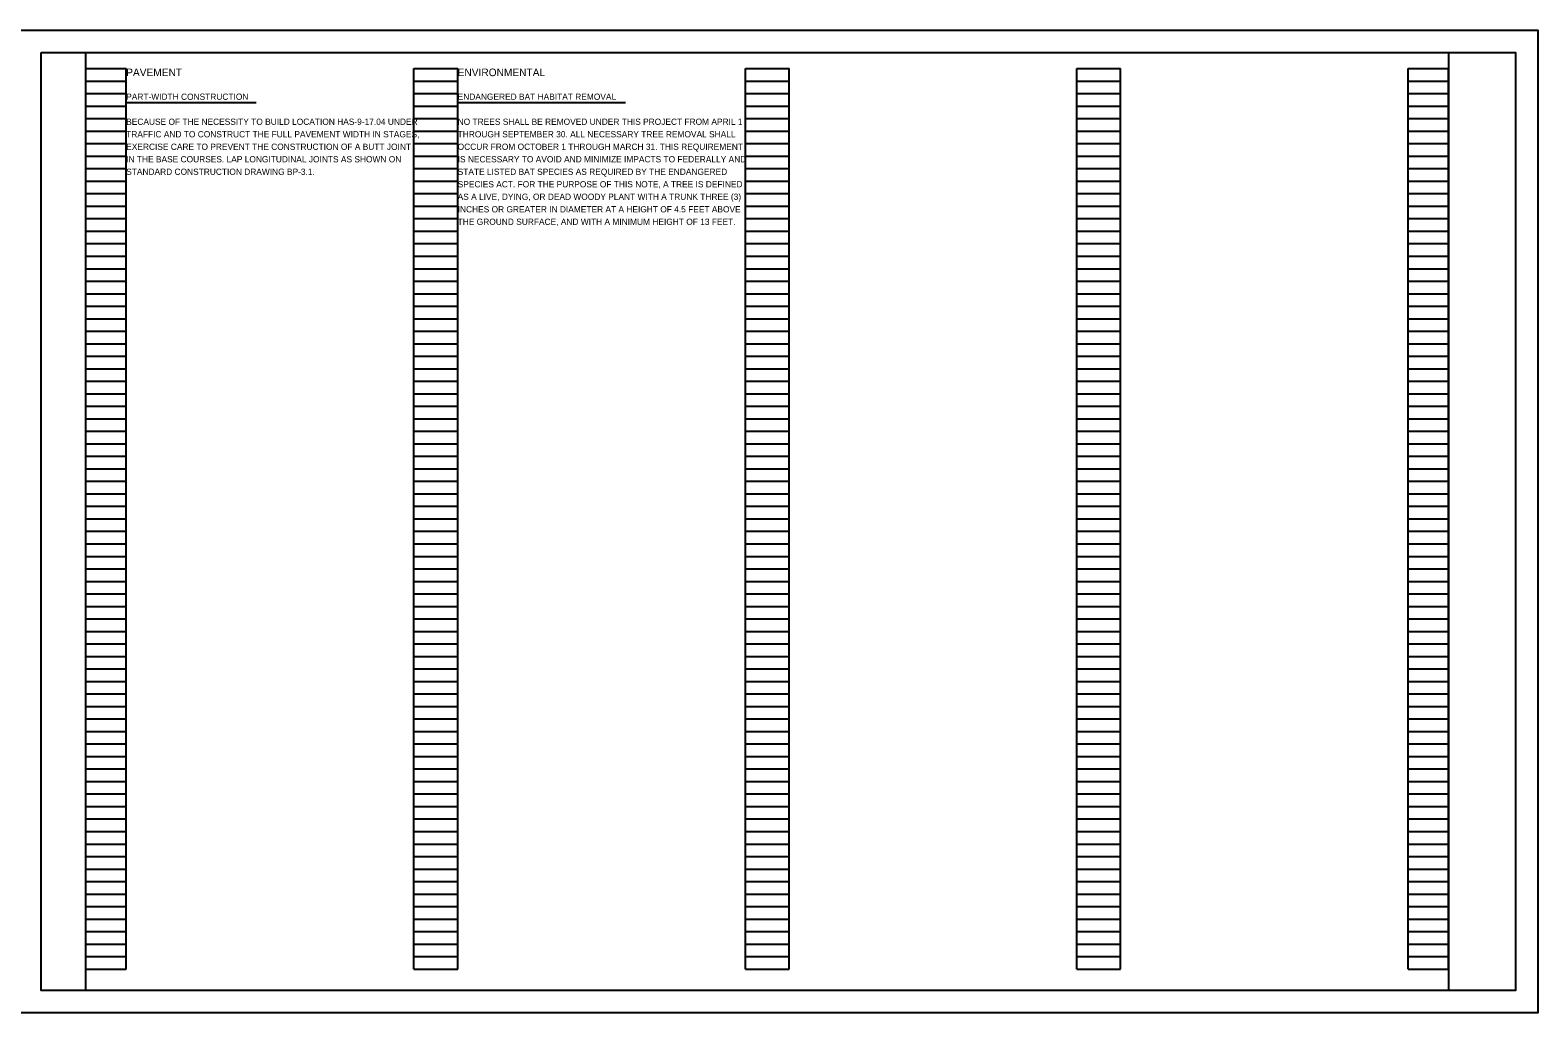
# Model space of a CAD drawing. Extents: x 0 to 102, y 0 to 22.
# Drawn here: x 68.25 to 102, y 0 to 22 of the extents above; entities that cross this region are included whole.
import ezdxf

# ---------------------------------------------------------------- set-up
doc = ezdxf.new("R2010")
doc.units = 0
doc.layers.add('SC_Scratch1', color=7, linetype='Continuous')
doc.layers.add('SH_Text', color=7, linetype='Continuous')

msp = doc.modelspace()

# ---------------------------------------------------------------- linework, layer by layer
at = {"layer": 'SC_Scratch1'}
for p, q in [((69.5, 0.98), (69.5, 21.14)), ((69.5, 21.14), (70.4, 21.14)), ((70.4, 0.98), (70.4, 21.14)), ((76.84, 0.98), (76.84, 21.14)), ((76.84, 21.14), (77.82, 21.14)), ((77.82, 0.98), (77.82, 21.14)), ((84.26, 0.98), (84.26, 21.14)), ((84.26, 21.14), (85.24, 21.14)), ((85.24, 0.98), (85.24, 21.14)), ((91.68, 0.98), (91.68, 21.14)), ((91.68, 21.14), (92.66, 21.14)), ((92.66, 0.98), (92.66, 21.14)), ((99.1, 0.98), (99.1, 21.14)), ((99.1, 21.14), (100, 21.14)), ((100, 0.98), (100, 21.14)), ((69.5, 20.86), (70.4, 20.86)), ((76.84, 20.86), (77.82, 20.86)), ((84.26, 20.86), (85.24, 20.86)), ((91.68, 20.86), (92.66, 20.86)), ((99.1, 20.86), (100, 20.86)), ((69.5, 20.58), (70.4, 20.58)), ((69.5, 20.3), (70.4, 20.3)), ((76.84, 20.58), (77.82, 20.58)), ((76.84, 20.3), (77.82, 20.3)), ((84.26, 20.58), (85.24, 20.58)), ((84.26, 20.3), (85.24, 20.3)), ((91.68, 20.58), (92.66, 20.58)), ((91.68, 20.3), (92.66, 20.3)), ((99.1, 20.58), (100, 20.58)), ((99.1, 20.3), (100, 20.3)), ((69.5, 20.02), (70.4, 20.02)), ((76.84, 20.02), (77.82, 20.02)), ((84.26, 20.02), (85.24, 20.02)), ((91.68, 20.02), (92.66, 20.02)), ((99.1, 20.02), (100, 20.02)), ((69.5, 19.74), (70.4, 19.74)), ((76.84, 19.74), (77.82, 19.74)), ((84.26, 19.74), (85.24, 19.74)), ((91.68, 19.74), (92.66, 19.74)), ((99.1, 19.74), (100, 19.74)), ((69.5, 19.46), (70.4, 19.46)), ((76.84, 19.46), (77.82, 19.46)), ((84.26, 19.46), (85.24, 19.46)), ((91.68, 19.46), (92.66, 19.46)), ((99.1, 19.46), (100, 19.46)), ((69.5, 19.18), (70.4, 19.18)), ((76.84, 19.18), (77.82, 19.18)), ((84.26, 19.18), (85.24, 19.18)), ((91.68, 19.18), (92.66, 19.18)), ((99.1, 19.18), (100, 19.18)), ((69.5, 18.9), (70.4, 18.9)), ((69.5, 18.62), (70.4, 18.62)), ((76.84, 18.9), (77.82, 18.9)), ((76.84, 18.62), (77.82, 18.62)), ((84.26, 18.9), (85.24, 18.9)), ((84.26, 18.62), (85.24, 18.62)), ((91.68, 18.9), (92.66, 18.9)), ((91.68, 18.62), (92.66, 18.62)), ((99.1, 18.9), (100, 18.9)), ((99.1, 18.62), (100, 18.62)), ((69.5, 18.34), (70.4, 18.34)), ((76.84, 18.34), (77.82, 18.34)), ((84.26, 18.34), (85.24, 18.34)), ((91.68, 18.34), (92.66, 18.34)), ((99.1, 18.34), (100, 18.34)), ((69.5, 18.06), (70.4, 18.06)), ((76.84, 18.06), (77.82, 18.06)), ((84.26, 18.06), (85.24, 18.06)), ((91.68, 18.06), (92.66, 18.06)), ((99.1, 18.06), (100, 18.06)), ((69.5, 17.78), (70.4, 17.78)), ((76.84, 17.78), (77.82, 17.78)), ((84.26, 17.78), (85.24, 17.78)), ((91.68, 17.78), (92.66, 17.78)), ((99.1, 17.78), (100, 17.78)), ((69.5, 17.5), (70.4, 17.5)), ((69.5, 17.22), (70.4, 17.22)), ((76.84, 17.5), (77.82, 17.5)), ((76.84, 17.22), (77.82, 17.22)), ((84.26, 17.5), (85.24, 17.5)), ((84.26, 17.22), (85.24, 17.22)), ((91.68, 17.5), (92.66, 17.5)), ((91.68, 17.22), (92.66, 17.22)), ((99.1, 17.5), (100, 17.5)), ((99.1, 17.22), (100, 17.22)), ((69.5, 16.94), (70.4, 16.94)), ((76.84, 16.94), (77.82, 16.94)), ((84.26, 16.94), (85.24, 16.94)), ((91.68, 16.94), (92.66, 16.94)), ((99.1, 16.94), (100, 16.94)), ((69.5, 16.66), (70.4, 16.66)), ((76.84, 16.66), (77.82, 16.66)), ((84.26, 16.66), (85.24, 16.66)), ((91.68, 16.66), (92.66, 16.66)), ((99.1, 16.66), (100, 16.66)), ((69.5, 16.38), (70.4, 16.38)), ((76.84, 16.38), (77.82, 16.38)), ((84.26, 16.38), (85.24, 16.38)), ((91.68, 16.38), (92.66, 16.38)), ((99.1, 16.38), (100, 16.38)), ((69.5, 16.1), (70.4, 16.1)), ((76.84, 16.1), (77.82, 16.1)), ((84.26, 16.1), (85.24, 16.1)), ((91.68, 16.1), (92.66, 16.1)), ((99.1, 16.1), (100, 16.1)), ((69.5, 15.82), (70.4, 15.82)), ((69.5, 15.54), (70.4, 15.54)), ((76.84, 15.82), (77.82, 15.82)), ((76.84, 15.54), (77.82, 15.54)), ((84.26, 15.82), (85.24, 15.82)), ((84.26, 15.54), (85.24, 15.54)), ((91.68, 15.82), (92.66, 15.82)), ((91.68, 15.54), (92.66, 15.54)), ((99.1, 15.82), (100, 15.82)), ((99.1, 15.54), (100, 15.54)), ((69.5, 15.26), (70.4, 15.26)), ((76.84, 15.26), (77.82, 15.26)), ((84.26, 15.26), (85.24, 15.26)), ((91.68, 15.26), (92.66, 15.26)), ((99.1, 15.26), (100, 15.26)), ((69.5, 14.98), (70.4, 14.98)), ((76.84, 14.98), (77.82, 14.98)), ((84.26, 14.98), (85.24, 14.98)), ((91.68, 14.98), (92.66, 14.98)), ((99.1, 14.98), (100, 14.98)), ((69.5, 14.7), (70.4, 14.7)), ((76.84, 14.7), (77.82, 14.7)), ((84.26, 14.7), (85.24, 14.7)), ((91.68, 14.7), (92.66, 14.7)), ((99.1, 14.7), (100, 14.7)), ((69.5, 14.42), (70.4, 14.42)), ((76.84, 14.42), (77.82, 14.42)), ((84.26, 14.42), (85.24, 14.42)), ((91.68, 14.42), (92.66, 14.42)), ((99.1, 14.42), (100, 14.42)), ((69.5, 14.14), (70.4, 14.14)), ((69.5, 13.86), (70.4, 13.86)), ((76.84, 14.14), (77.82, 14.14)), ((76.84, 13.86), (77.82, 13.86)), ((84.26, 14.14), (85.24, 14.14)), ((84.26, 13.86), (85.24, 13.86)), ((91.68, 14.14), (92.66, 14.14)), ((91.68, 13.86), (92.66, 13.86)), ((99.1, 14.14), (100, 14.14)), ((99.1, 13.86), (100, 13.86)), ((69.5, 13.58), (70.4, 13.58)), ((76.84, 13.58), (77.82, 13.58)), ((84.26, 13.58), (85.24, 13.58)), ((91.68, 13.58), (92.66, 13.58)), ((99.1, 13.58), (100, 13.58)), ((69.5, 13.3), (70.4, 13.3)), ((76.84, 13.3), (77.82, 13.3)), ((84.26, 13.3), (85.24, 13.3)), ((91.68, 13.3), (92.66, 13.3)), ((99.1, 13.3), (100, 13.3)), ((69.5, 13.02), (70.4, 13.02)), ((76.84, 13.02), (77.82, 13.02)), ((84.26, 13.02), (85.24, 13.02)), ((91.68, 13.02), (92.66, 13.02)), ((99.1, 13.02), (100, 13.02)), ((69.5, 12.74), (70.4, 12.74)), ((76.84, 12.74), (77.82, 12.74)), ((84.26, 12.74), (85.24, 12.74)), ((91.68, 12.74), (92.66, 12.74)), ((99.1, 12.74), (100, 12.74)), ((69.5, 12.46), (70.4, 12.46)), ((69.5, 12.18), (70.4, 12.18)), ((76.84, 12.46), (77.82, 12.46)), ((76.84, 12.18), (77.82, 12.18)), ((84.26, 12.46), (85.24, 12.46)), ((84.26, 12.18), (85.24, 12.18)), ((91.68, 12.46), (92.66, 12.46)), ((91.68, 12.18), (92.66, 12.18)), ((99.1, 12.46), (100, 12.46)), ((99.1, 12.18), (100, 12.18)), ((69.5, 11.9), (70.4, 11.9)), ((76.84, 11.9), (77.82, 11.9)), ((84.26, 11.9), (85.24, 11.9)), ((91.68, 11.9), (92.66, 11.9)), ((99.1, 11.9), (100, 11.9)), ((69.5, 11.62), (70.4, 11.62)), ((76.84, 11.62), (77.82, 11.62)), ((84.26, 11.62), (85.24, 11.62)), ((91.68, 11.62), (92.66, 11.62)), ((99.1, 11.62), (100, 11.62)), ((69.5, 11.34), (70.4, 11.34)), ((76.84, 11.34), (77.82, 11.34)), ((84.26, 11.34), (85.24, 11.34)), ((91.68, 11.34), (92.66, 11.34)), ((99.1, 11.34), (100, 11.34)), ((69.5, 11.06), (70.4, 11.06)), ((76.84, 11.06), (77.82, 11.06)), ((84.26, 11.06), (85.24, 11.06)), ((91.68, 11.06), (92.66, 11.06)), ((99.1, 11.06), (100, 11.06)), ((69.5, 10.78), (70.4, 10.78)), ((69.5, 10.5), (70.4, 10.5)), ((76.84, 10.78), (77.82, 10.78)), ((76.84, 10.5), (77.82, 10.5)), ((84.26, 10.78), (85.24, 10.78)), ((84.26, 10.5), (85.24, 10.5)), ((91.68, 10.78), (92.66, 10.78)), ((91.68, 10.5), (92.66, 10.5)), ((99.1, 10.78), (100, 10.78)), ((99.1, 10.5), (100, 10.5)), ((69.5, 10.22), (70.4, 10.22)), ((76.84, 10.22), (77.82, 10.22)), ((84.26, 10.22), (85.24, 10.22)), ((91.68, 10.22), (92.66, 10.22)), ((99.1, 10.22), (100, 10.22)), ((69.5, 9.94), (70.4, 9.94)), ((76.84, 9.94), (77.82, 9.94)), ((84.26, 9.94), (85.24, 9.94)), ((91.68, 9.94), (92.66, 9.94)), ((99.1, 9.94), (100, 9.94)), ((69.5, 9.66), (70.4, 9.66)), ((76.84, 9.66), (77.82, 9.66)), ((84.26, 9.66), (85.24, 9.66)), ((91.68, 9.66), (92.66, 9.66)), ((99.1, 9.66), (100, 9.66)), ((69.5, 9.38), (70.4, 9.38)), ((76.84, 9.38), (77.82, 9.38)), ((84.26, 9.38), (85.24, 9.38)), ((91.68, 9.38), (92.66, 9.38)), ((99.1, 9.38), (100, 9.38)), ((69.5, 9.1), (70.4, 9.1)), ((69.5, 8.82), (70.4, 8.82)), ((76.84, 9.1), (77.82, 9.1)), ((76.84, 8.82), (77.82, 8.82)), ((84.26, 9.1), (85.24, 9.1)), ((84.26, 8.82), (85.24, 8.82)), ((91.68, 9.1), (92.66, 9.1)), ((91.68, 8.82), (92.66, 8.82)), ((99.1, 9.1), (100, 9.1)), ((99.1, 8.82), (100, 8.82)), ((69.5, 8.54), (70.4, 8.54)), ((76.84, 8.54), (77.82, 8.54)), ((84.26, 8.54), (85.24, 8.54)), ((91.68, 8.54), (92.66, 8.54)), ((99.1, 8.54), (100, 8.54)), ((69.5, 8.26), (70.4, 8.26)), ((76.84, 8.26), (77.82, 8.26)), ((84.26, 8.26), (85.24, 8.26)), ((91.68, 8.26), (92.66, 8.26)), ((99.1, 8.26), (100, 8.26)), ((69.5, 7.98), (70.4, 7.98)), ((76.84, 7.98), (77.82, 7.98)), ((84.26, 7.98), (85.24, 7.98)), ((91.68, 7.98), (92.66, 7.98)), ((99.1, 7.98), (100, 7.98)), ((69.5, 7.7), (70.4, 7.7)), ((76.84, 7.7), (77.82, 7.7)), ((84.26, 7.7), (85.24, 7.7)), ((91.68, 7.7), (92.66, 7.7)), ((99.1, 7.7), (100, 7.7)), ((69.5, 7.42), (70.4, 7.42)), ((69.5, 7.14), (70.4, 7.14)), ((76.84, 7.42), (77.82, 7.42)), ((76.84, 7.14), (77.82, 7.14)), ((84.26, 7.42), (85.24, 7.42)), ((84.26, 7.14), (85.24, 7.14)), ((91.68, 7.42), (92.66, 7.42)), ((91.68, 7.14), (92.66, 7.14)), ((99.1, 7.42), (100, 7.42)), ((99.1, 7.14), (100, 7.14)), ((69.5, 6.86), (70.4, 6.86)), ((76.84, 6.86), (77.82, 6.86)), ((84.26, 6.86), (85.24, 6.86)), ((91.68, 6.86), (92.66, 6.86)), ((99.1, 6.86), (100, 6.86)), ((69.5, 6.58), (70.4, 6.58)), ((76.84, 6.58), (77.82, 6.58)), ((84.26, 6.58), (85.24, 6.58)), ((91.68, 6.58), (92.66, 6.58)), ((99.1, 6.58), (100, 6.58)), ((69.5, 6.3), (70.4, 6.3)), ((76.84, 6.3), (77.82, 6.3)), ((84.26, 6.3), (85.24, 6.3)), ((91.68, 6.3), (92.66, 6.3)), ((99.1, 6.3), (100, 6.3)), ((69.5, 6.02), (70.4, 6.02)), ((69.5, 5.74), (70.4, 5.74)), ((76.84, 6.02), (77.82, 6.02)), ((76.84, 5.74), (77.82, 5.74)), ((84.26, 6.02), (85.24, 6.02)), ((84.26, 5.74), (85.24, 5.74)), ((91.68, 6.02), (92.66, 6.02)), ((91.68, 5.74), (92.66, 5.74)), ((99.1, 6.02), (100, 6.02)), ((99.1, 5.74), (100, 5.74)), ((69.5, 5.46), (70.4, 5.46)), ((76.84, 5.46), (77.82, 5.46)), ((84.26, 5.46), (85.24, 5.46)), ((91.68, 5.46), (92.66, 5.46)), ((99.1, 5.46), (100, 5.46)), ((69.5, 5.18), (70.4, 5.18)), ((76.84, 5.18), (77.82, 5.18)), ((84.26, 5.18), (85.24, 5.18)), ((91.68, 5.18), (92.66, 5.18)), ((99.1, 5.18), (100, 5.18)), ((69.5, 4.9), (70.4, 4.9)), ((76.84, 4.9), (77.82, 4.9)), ((84.26, 4.9), (85.24, 4.9)), ((91.68, 4.9), (92.66, 4.9)), ((99.1, 4.9), (100, 4.9)), ((69.5, 4.62), (70.4, 4.62)), ((76.84, 4.62), (77.82, 4.62)), ((84.26, 4.62), (85.24, 4.62)), ((91.68, 4.62), (92.66, 4.62)), ((99.1, 4.62), (100, 4.62)), ((69.5, 4.34), (70.4, 4.34)), ((69.5, 4.06), (70.4, 4.06)), ((76.84, 4.34), (77.82, 4.34)), ((76.84, 4.06), (77.82, 4.06)), ((84.26, 4.34), (85.24, 4.34)), ((84.26, 4.06), (85.24, 4.06)), ((91.68, 4.34), (92.66, 4.34)), ((91.68, 4.06), (92.66, 4.06)), ((99.1, 4.34), (100, 4.34)), ((99.1, 4.06), (100, 4.06)), ((69.5, 3.78), (70.4, 3.78)), ((76.84, 3.78), (77.82, 3.78)), ((84.26, 3.78), (85.24, 3.78)), ((91.68, 3.78), (92.66, 3.78)), ((99.1, 3.78), (100, 3.78)), ((69.5, 3.5), (70.4, 3.5)), ((76.84, 3.5), (77.82, 3.5)), ((84.26, 3.5), (85.24, 3.5)), ((91.68, 3.5), (92.66, 3.5)), ((99.1, 3.5), (100, 3.5)), ((69.5, 3.22), (70.4, 3.22)), ((76.84, 3.22), (77.82, 3.22)), ((84.26, 3.22), (85.24, 3.22)), ((91.68, 3.22), (92.66, 3.22)), ((99.1, 3.22), (100, 3.22)), ((69.5, 2.94), (70.4, 2.94)), ((76.84, 2.94), (77.82, 2.94)), ((84.26, 2.94), (85.24, 2.94)), ((91.68, 2.94), (92.66, 2.94)), ((99.1, 2.94), (100, 2.94)), ((69.5, 2.66), (70.4, 2.66)), ((69.5, 2.38), (70.4, 2.38)), ((76.84, 2.66), (77.82, 2.66)), ((76.84, 2.38), (77.82, 2.38)), ((84.26, 2.66), (85.24, 2.66)), ((84.26, 2.38), (85.24, 2.38)), ((91.68, 2.66), (92.66, 2.66)), ((91.68, 2.38), (92.66, 2.38)), ((99.1, 2.66), (100, 2.66)), ((99.1, 2.38), (100, 2.38)), ((69.5, 2.1), (70.4, 2.1)), ((76.84, 2.1), (77.82, 2.1)), ((84.26, 2.1), (85.24, 2.1)), ((91.68, 2.1), (92.66, 2.1)), ((99.1, 2.1), (100, 2.1)), ((69.5, 1.82), (70.4, 1.82)), ((76.84, 1.82), (77.82, 1.82)), ((84.26, 1.82), (85.24, 1.82)), ((91.68, 1.82), (92.66, 1.82)), ((99.1, 1.82), (100, 1.82)), ((69.5, 1.54), (70.4, 1.54)), ((76.84, 1.54), (77.82, 1.54)), ((84.26, 1.54), (85.24, 1.54)), ((91.68, 1.54), (92.66, 1.54)), ((99.1, 1.54), (100, 1.54)), ((69.5, 1.26), (70.4, 1.26)), ((76.84, 1.26), (77.82, 1.26)), ((84.26, 1.26), (85.24, 1.26)), ((91.68, 1.26), (92.66, 1.26)), ((99.1, 1.26), (100, 1.26)), ((69.5, 0.98), (70.4, 0.98)), ((76.84, 0.98), (77.82, 0.98)), ((84.26, 0.98), (85.24, 0.98)), ((91.68, 0.98), (92.66, 0.98)), ((99.1, 0.98), (100, 0.98))]:
    msp.add_line(p, q, dxfattribs=at)
for points in [[(68, 22), (102, 22), (102, 0), (68, 0)], [(68.5, 21.5), (101.5, 21.5), (101.5, 0.5), (68.5, 0.5)], [(69.5, 21.5), (100, 21.5), (100, 0.5), (69.5, 0.5)]]:
    msp.add_lwpolyline(points, close=True, dxfattribs=at)
at = {"layer": 'SH_Text'}
for p, q in [((70.4, 20.379), (73.31, 20.379)), ((77.82, 20.379), (81.575, 20.379))]:
    msp.add_line(p, q, dxfattribs=at)

# ---------------------------------------------------------------- texts
for s, height, p in [('PAVEMENT', 0.17, (70.4, 20.97)), ('ENVIRONMENTAL', 0.17, (77.82, 20.97)), ('PART-WIDTH CONSTRUCTION', 0.14, (70.4, 20.44)), ('ENDANGERED BAT HABITAT REMOVAL', 0.14, (77.82, 20.44)), ('BECAUSE OF THE NECESSITY TO BUILD LOCATION HAS-9-17.04 UNDER', 0.14, (70.4, 19.88)), ('NO TREES SHALL BE REMOVED UNDER THIS PROJECT FROM APRIL 1', 0.14, (77.82, 19.88)), ('TRAFFIC AND TO CONSTRUCT THE FULL PAVEMENT WIDTH IN STAGES, ', 0.14, (70.4, 19.6)), ('THROUGH SEPTEMBER 30. ALL NECESSARY TREE REMOVAL SHALL', 0.14, (77.82, 19.6)), ('EXERCISE CARE TO PREVENT THE CONSTRUCTION OF A BUTT JOINT ', 0.14, (70.4, 19.32)), ('OCCUR FROM OCTOBER 1 THROUGH MARCH 31. THIS REQUIREMENT', 0.14, (77.82, 19.32)), ('STANDARD CONSTRUCTION DRAWING BP-3.1.', 0.14, (70.4, 18.76)), ('IN THE BASE COURSES. LAP LONGITUDINAL JOINTS AS SHOWN ON ', 0.14, (70.4, 19.04)), ('STATE LISTED BAT SPECIES AS REQUIRED BY THE ENDANGERED', 0.14, (77.82, 18.76)), ('IS NECESSARY TO AVOID AND MINIMIZE IMPACTS TO FEDERALLY AND', 0.14, (77.82, 19.04)), ('SPECIES ACT. FOR THE PURPOSE OF THIS NOTE, A TREE IS DEFINED', 0.14, (77.82, 18.48)), ('AS A LIVE, DYING, OR DEAD WOODY PLANT WITH A TRUNK THREE (3)', 0.14, (77.82, 18.2)), ('INCHES OR GREATER IN DIAMETER AT A HEIGHT OF 4.5 FEET ABOVE', 0.14, (77.82, 17.92)), ('THE GROUND SURFACE, AND WITH A MINIMUM HEIGHT OF 13 FEET.', 0.14, (77.82, 17.64))]:
    msp.add_text(s, height=height, dxfattribs=at).set_placement(p)

doc.saveas('drawing.dxf')
